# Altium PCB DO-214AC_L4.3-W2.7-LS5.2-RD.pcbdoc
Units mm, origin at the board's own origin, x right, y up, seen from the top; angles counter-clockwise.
Board outline 19.3 x 15.5 mm, 2 copper layers (Top Layer, Bottom Layer), stack 0 mm thick; 1 components, 0 nets, 2 pads, 0 vias.
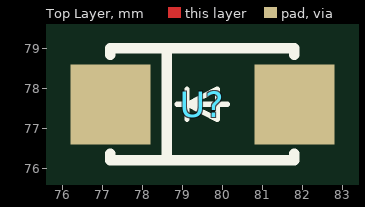
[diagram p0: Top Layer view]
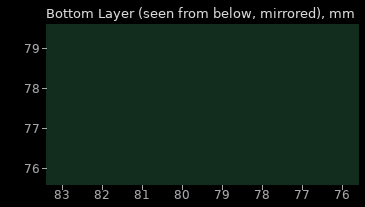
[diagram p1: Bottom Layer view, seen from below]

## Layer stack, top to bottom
Top Layer: signal copper (thickness not stored)
Bottom Layer: signal copper (thickness not stored)

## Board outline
89.15,69.85 69.85,69.85 69.85,85.35 89.15,85.35

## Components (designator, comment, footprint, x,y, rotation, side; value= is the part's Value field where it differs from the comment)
U? "" DO-214AC_L4.3-W2.7-LS5.2-RD 79.5,77.6 r0 top

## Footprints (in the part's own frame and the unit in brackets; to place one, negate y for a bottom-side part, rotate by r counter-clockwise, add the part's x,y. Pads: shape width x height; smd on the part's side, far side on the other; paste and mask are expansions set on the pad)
DO-214AC_L4.3-W2.7-LS5.2-RD [mm]
  rect 2x2 smd: 1(-2.3,0) 2(2.3,0)
  silkscreen extent -2.3,-1.4 2.3,1.4

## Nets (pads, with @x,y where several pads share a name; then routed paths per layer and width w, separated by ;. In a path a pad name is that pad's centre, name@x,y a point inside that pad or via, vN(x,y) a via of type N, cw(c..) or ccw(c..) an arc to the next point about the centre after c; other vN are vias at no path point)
pads on no net: U?.1 U?.2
